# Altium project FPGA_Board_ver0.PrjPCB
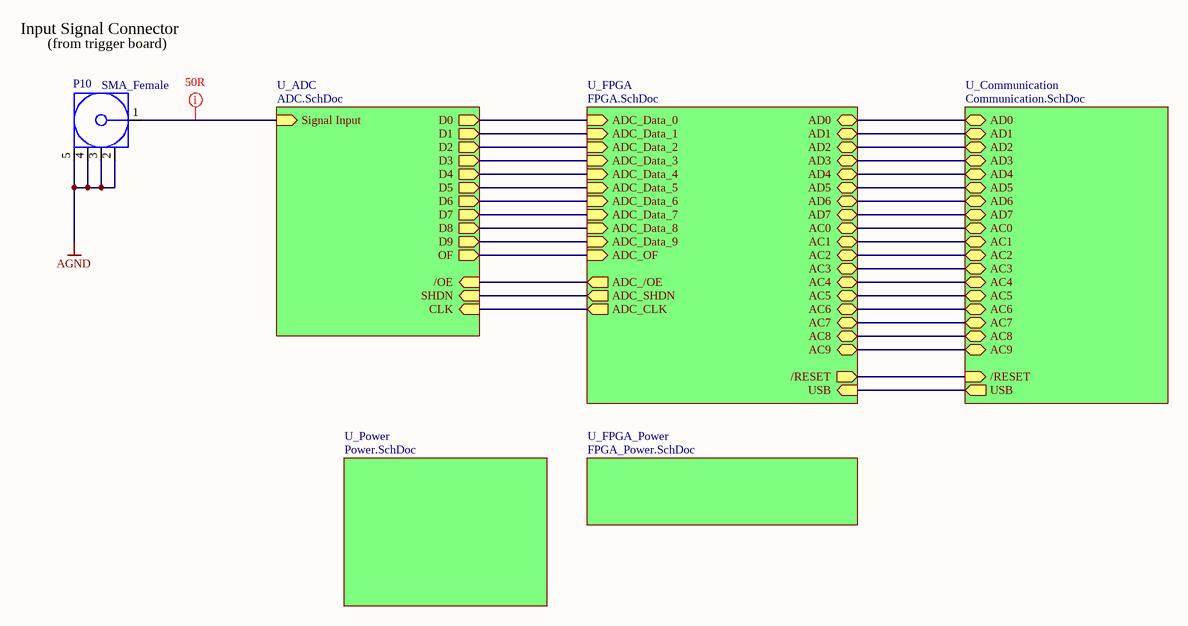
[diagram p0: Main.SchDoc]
6 sheets, 303 parts. Net scope: hierarchical (ports join the sheet entries above them; power ports are global).
Board file: FPGA_Board.PcbDoc
Sheets:
  Main.SchDoc
    U_ADC = ADC.SchDoc
    U_Communication = Communication.SchDoc
    U_FPGA = FPGA.SchDoc
    U_FPGA_Power = FPGA_Power.SchDoc
    U_Power = Power.SchDoc

## Sheet Main.SchDoc
size A4

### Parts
P10  SMA_Female  [SMA5.08-H]

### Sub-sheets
U_ADC = ADC.SchDoc: Signal Input (in), D0 (out), D1 (out), D2 (out), D3 (out), D4 (out), D5 (out), D6 (out), D7 (out), D8 (out), D9 (out), OF (out), CLK (in), SHDN (in), /OE (in)
U_Communication = Communication.SchDoc: AD0 (bidir), AD1 (bidir), AD2 (bidir), AD3 (bidir), AD4 (bidir), AD5 (bidir), AD6 (bidir), AD7 (bidir), AC0 (bidir), AC1 (bidir), AC2 (bidir), AC3 (bidir), AC4 (bidir), AC5 (bidir), AC6 (bidir), AC7 (bidir), AC8 (bidir), AC9 (bidir), /RESET (in), USB (out)
U_FPGA = FPGA.SchDoc: ADC_Data_0 (in), ADC_Data_1 (in), ADC_Data_2 (in), ADC_Data_3 (in), ADC_Data_4 (in), ADC_Data_5 (in), ADC_Data_6 (in), ADC_Data_7 (in), ADC_Data_8 (in), ADC_Data_9 (in), ADC_CLK (out), ADC_OF (in), ADC_/OE (out), ADC_SHDN (out), AD0 (bidir), AD1 (bidir), AD2 (bidir), AD3 (bidir), AD4 (bidir), AD5 (bidir), AD6 (bidir), AD7 (bidir), AC0 (bidir), AC1 (bidir), AC2 (bidir), AC3 (bidir), AC4 (bidir), AC5 (bidir), AC6 (bidir), AC7 (bidir), AC8 (bidir), AC9 (bidir), /RESET (out), USB (in)
U_FPGA_Power = FPGA_Power.SchDoc: no entries
U_Power = Power.SchDoc: no entries

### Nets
AGND: P10.2(GND) P10.3(GND) P10.4(GND) P10.5(GND)
/RESET: sheet U_Communication//RESET, sheet U_FPGA//RESET
NetC16_2: P10.1(Signal) ; sheet U_ADC/Signal Input
NetC41_2: sheet U_Communication/USB, sheet U_FPGA/USB
NetR41_2: sheet U_Communication/AC9, sheet U_FPGA/AC9
NetR42_2: sheet U_Communication/AC8, sheet U_FPGA/AC8
NetR43_2: sheet U_Communication/AC7, sheet U_FPGA/AC7
NetR44_2: sheet U_Communication/AC6, sheet U_FPGA/AC6
NetR45_2: sheet U_Communication/AC5, sheet U_FPGA/AC5
NetR51_2: sheet U_Communication/AC4, sheet U_FPGA/AC4
NetR54_2: sheet U_Communication/AC3, sheet U_FPGA/AC3
NetR55_2: sheet U_Communication/AC2, sheet U_FPGA/AC2
NetR56_2: sheet U_Communication/AC1, sheet U_FPGA/AC1
NetR61_2: sheet U_Communication/AC0, sheet U_FPGA/AC0
NetR66_2: sheet U_Communication/AD7, sheet U_FPGA/AD7
NetR67_2: sheet U_Communication/AD6, sheet U_FPGA/AD6
NetR68_2: sheet U_Communication/AD5, sheet U_FPGA/AD5
NetR71_2: sheet U_Communication/AD4, sheet U_FPGA/AD4
NetR75_2: sheet U_Communication/AD3, sheet U_FPGA/AD3
NetR78_2: sheet U_Communication/AD2, sheet U_FPGA/AD2
NetR79_2: sheet U_Communication/AD1, sheet U_FPGA/AD1
NetR80_2: sheet U_Communication/AD0, sheet U_FPGA/AD0
NetU1_9: sheet U_ADC/CLK, sheet U_FPGA/ADC_CLK
NetU1_10: sheet U_ADC/SHDN, sheet U_FPGA/ADC_SHDN
NetU1_11: sheet U_ADC//OE, sheet U_FPGA/ADC_/OE
NetU1_16: sheet U_ADC/D0, sheet U_FPGA/ADC_Data_0
NetU1_17: sheet U_ADC/D1, sheet U_FPGA/ADC_Data_1
NetU1_18: sheet U_ADC/D2, sheet U_FPGA/ADC_Data_2
NetU1_19: sheet U_ADC/D3, sheet U_FPGA/ADC_Data_3
NetU1_22: sheet U_ADC/D4, sheet U_FPGA/ADC_Data_4
NetU1_23: sheet U_ADC/D5, sheet U_FPGA/ADC_Data_5
NetU1_24: sheet U_ADC/D6, sheet U_FPGA/ADC_Data_6
NetU1_25: sheet U_ADC/D7, sheet U_FPGA/ADC_Data_7
NetU1_26: sheet U_ADC/D8, sheet U_FPGA/ADC_Data_8
NetU1_27: sheet U_ADC/D9, sheet U_FPGA/ADC_Data_9
NetU1_28: sheet U_ADC/OF, sheet U_FPGA/ADC_OF

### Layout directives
net class 50R: NetC16_2

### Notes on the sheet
- Input Signal Connector
- (from trigger board)

## Sheet ADC.SchDoc
size A4
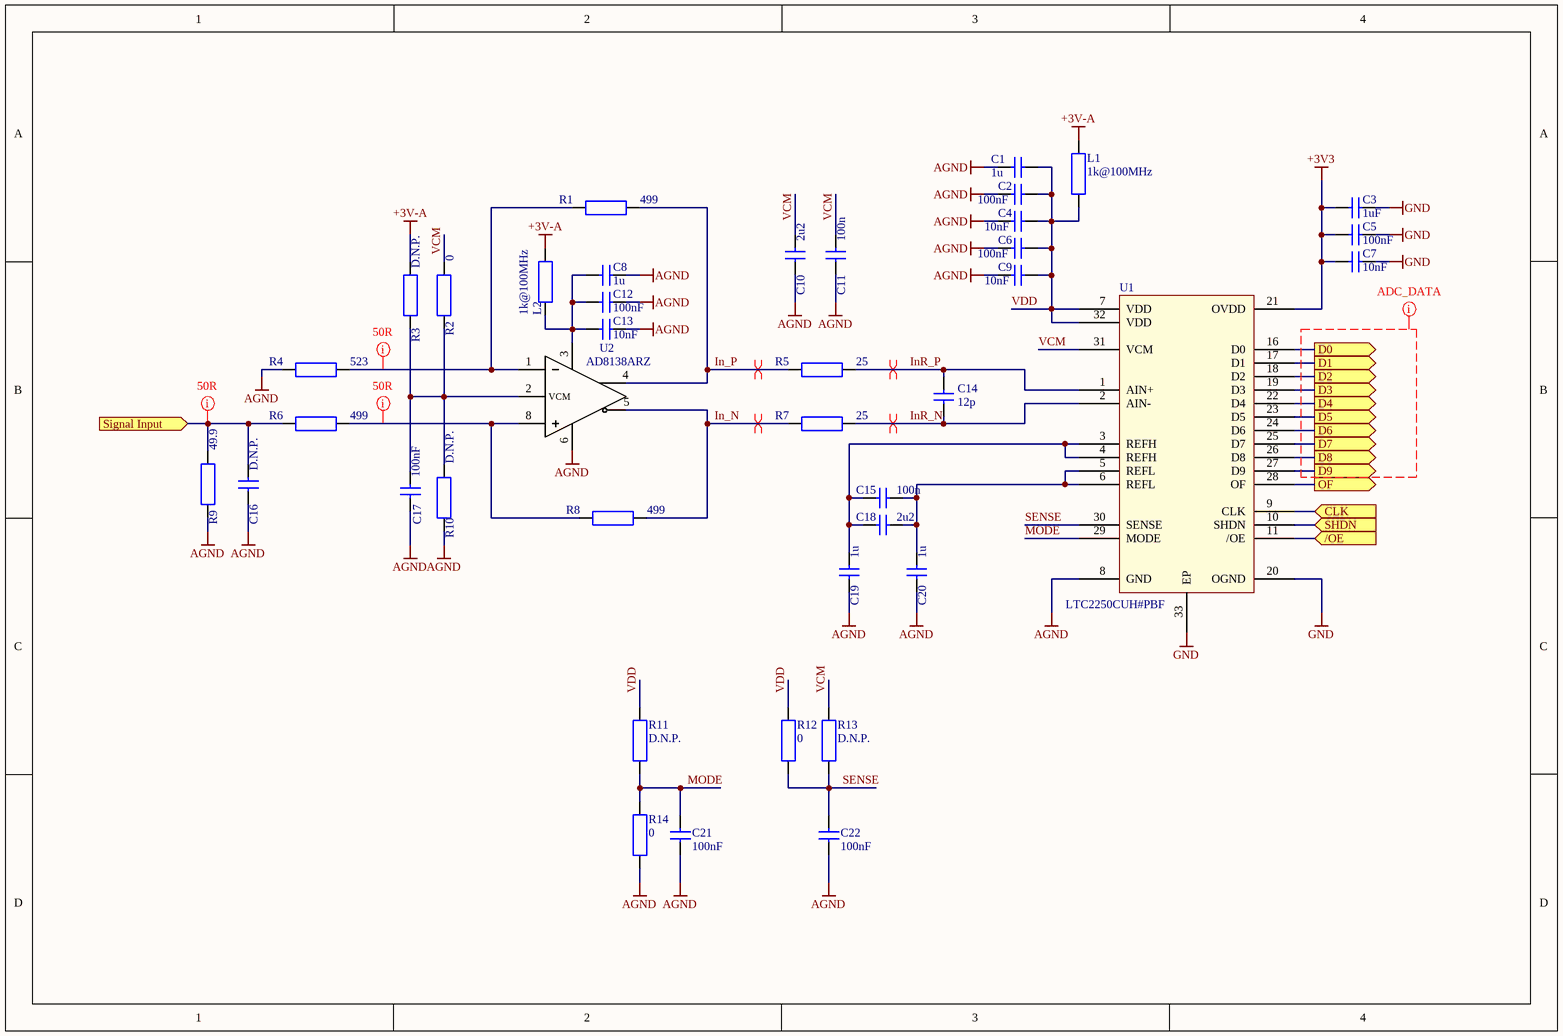
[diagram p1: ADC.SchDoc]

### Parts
C1  1u  [SMD_CAPACITOR_0603]
C2  100nF  [SMD_CAPACITOR_0603]
C3  1uF  [SMD_CAPACITOR_0603]
C4  10nF  [SMD_CAPACITOR_0603]
C5  100nF  [SMD_CAPACITOR_0603]
C6  100nF  [SMD_CAPACITOR_0603]
C7  10nF  [SMD_CAPACITOR_0603]
C8  1u  [SMD_CAPACITOR_0603]
C9  10nF  [SMD_CAPACITOR_0603]
C10  2u2  [SMD_CAPACITOR_0603]
C11  100n  [SMD_CAPACITOR_0603]
C12  100nF  [SMD_CAPACITOR_0603]
C13  10nF  [SMD_CAPACITOR_0603]
C14  12p  [SMD_CAPACITOR_0603]
C15  100n  [SMD_CAPACITOR_0603]
C16  D.N.P.  [SMD_CAPACITOR_0603]
C17  100nF  [SMD_CAPACITOR_0603]
C18  2u2  [SMD_CAPACITOR_0603]
C19  1u  [SMD_CAPACITOR_0603]
C20  1u  [SMD_CAPACITOR_0603]
C21  100nF  [SMD_CAPACITOR_0603]
C22  100nF  [SMD_CAPACITOR_0603]
L1  1k@100MHz  [SMD_RES_0603]
L2  1k@100MHz  [SMD_RES_0603]
R1  499  [SMD_RES_0603]
R2  0  [SMD_RES_0603]
R3  D.N.P.  [SMD_RES_0603]
R4  523  [SMD_RES_0603]
R5  25  [SMD_RES_0603]
R6  499  [SMD_RES_0603]
R7  25  [SMD_RES_0603]
R8  499  [SMD_RES_0603]
R9  49.9  [SMD_RES_0603]
R10  D.N.P.  [SMD_RES_0603]
R11  D.N.P.  [SMD_RES_0603]
R12  0  [SMD_RES_0603]
R13  D.N.P.  [SMD_RES_0603]
R14  0  [SMD_RES_0603]
U1  LTC2250CUH#PBF  [QFN-32_5mm_x_5mm]
U2  AD8138ARZ  [SMD_SOIC-8]

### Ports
/OE (in), CLK (in), D0 (out), D1 (out), D2 (out), D3 (out), D4 (out), D5 (out), D6 (out), D7 (out), D8 (out), D9 (out), OF (out), SHDN (in), Signal Input (in)

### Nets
+3V3: C3.1 C5.1 C7.1 U1.21(OVDD)
+3V-A: L1.2 L2.2 R3.2
AGND: C1.2 C2.2 C4.2 C6.2 C8.2 C9.2 C10.1 C11.1 C12.2 C13.2 C16.1 C17.1 C19.1 C20.1 C21.2 C22.2 R4.1 R9.1 R10.1 R14.1 U1.8(GND) U2.6
GND: C3.2 C5.2 C7.2 U1.20(OGND) U1.33(EP)
In_N: R7.1 R8.2 U2.5
In_P: R1.2 R5.1 U2.4
InR_N: C14.1 R7.2 U1.2(AIN-)
InR_P: C14.2 R5.2 U1.1(AIN+)
MODE: C21.1 R11.1 R14.2 U1.29(MODE)
SENSE: C22.1 R12.1 R13.1 U1.30(SENSE)
VCM: C10.2 C11.2 R2.2 R13.2 U1.31(VCM)
VDD: C1.1 C2.1 C4.1 C6.1 C9.1 L1.1 R11.2 R12.2 U1.7(VDD) U1.32(VDD)
NetC8_1: C8.1 C12.1 C13.1 L2.1 U2.3
NetC15_1: C15.1 C18.1 C20.2 U1.5(REFL) U1.6(REFL)
NetC15_2: C15.2 C18.2 C19.2 U1.3(REFH) U1.4(REFH)
NetC16_2: C16.2 R6.1 R9.2 ; port Signal Input
NetC17_2: C17.2 R2.1 R3.1 R10.2 U2.2(VCM)
NetR1_1: R1.1 R4.2 U2.1
NetR6_2: R6.2 R8.1 U2.8
NetU1_9: U1.9(CLK) ; port CLK
NetU1_10: U1.10(SHDN) ; port SHDN
NetU1_11: U1.11(/OE) ; port /OE
NetU1_16: U1.16(D0) ; port D0
NetU1_17: U1.17(D1) ; port D1
NetU1_18: U1.18(D2) ; port D2
NetU1_19: U1.19(D3) ; port D3
NetU1_22: U1.22(D4) ; port D4
NetU1_23: U1.23(D5) ; port D5
NetU1_24: U1.24(D6) ; port D6
NetU1_25: U1.25(D7) ; port D7
NetU1_26: U1.26(D8) ; port D8
NetU1_27: U1.27(D9) ; port D9
NetU1_28: U1.28(OF) ; port OF

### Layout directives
net class 50R: NetC16_2, NetR1_1, NetR6_2
differential pair: In_N, In_P, InR_N, InR_P
net class ADC_DATA: (no net found under the mark)

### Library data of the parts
C1-C22 = Capacitor
L1 L2 = EMI_Ferrite_bead
R1-R14 = Resistor
U1 = LTC2250CUH#PBF: Analog to digital converter_10bit_105MS/s
U2 = AD8138ARZ: Low Distortion,Differential ADC Driver

## Sheet Communication.SchDoc
size A4
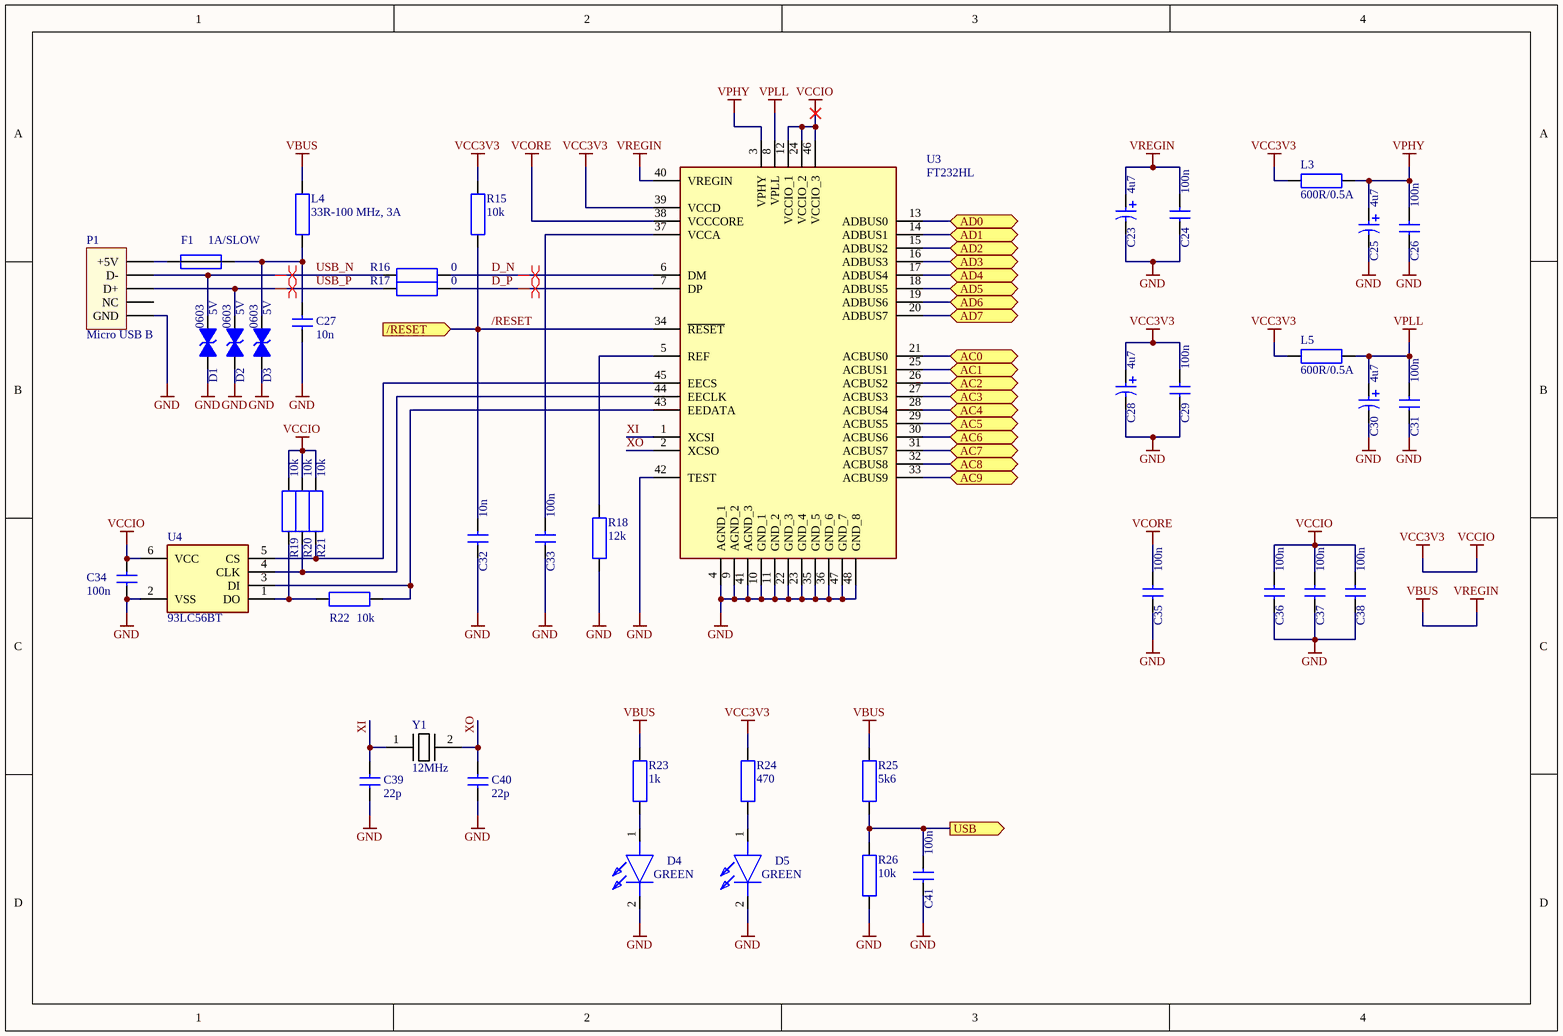
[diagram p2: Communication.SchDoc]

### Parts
C23  4u7  [SMD_CAPACITOR_POL_A_3216]
C24  100n  [SMD_CAPACITOR_0402]
C25  4u7  [SMD_CAPACITOR_POL_A_3216]
C26  100n  [SMD_CAPACITOR_0402]
C27  10n  [SMD_CAPACITOR_0603]
C28  4u7  [SMD_CAPACITOR_POL_A_3216]
C29  100n  [SMD_CAPACITOR_0402]
C30  4u7  [SMD_CAPACITOR_POL_A_3216]
C31  100n  [SMD_CAPACITOR_0402]
C32  10n  [SMD_CAPACITOR_0603]
C33  100n  [SMD_CAPACITOR_0402]
C34  100n  [SMD_CAPACITOR_0603]
C35  100n  [SMD_CAPACITOR_0402]
C36  100n  [SMD_CAPACITOR_0402]
C37  100n  [SMD_CAPACITOR_0402]
C38  100n  [SMD_CAPACITOR_0402]
C39  22p  [SMD_CAPACITOR_0603]
C40  22p  [SMD_CAPACITOR_0603]
C41  100n  [SMD_CAPACITOR_0603]
D1  5V  Package: 0603  [sm_esd_0603]
D2  5V  Package: 0603  [sm_esd_0603]
D3  5V  Package: 0603  [sm_esd_0603]
D4  GREEN  [SMD_LED_0603]
D5  GREEN  [SMD_LED_0603]
F1  1A/SLOW  [SMD_RESISTOR_1206]
L3  600R/0.5A  [SMD_RES_0603]
L4  33R-100 MHz, 3A  [SMD_RES_0603]
L5  600R/0.5A  [SMD_RES_0603]
P1  Micro USB B  [SMD_USB_MICRO_B]
R15  10k  [SMD_RES_0603]
R16  0  [SMD_RES_0603]
R17  0  [SMD_RES_0603]
R18  12k  [SMD_RES_0603]
R19  10k  [SMD_RES_0603]
R20  10k  [SMD_RES_0603]
R21  10k  [SMD_RES_0603]
R22  10k  [SMD_RES_0603]
R23  1k  [SMD_RES_0603]
R24  470  [SMD_RES_0603]
R25  5k6  [SMD_RES_0603]
R26  10k  [SMD_RES_0603]
U3  FT232HL  [QFP50P900X900X160-48N]
U4  93LC56BT  [SOT95P270X145-6N]
Y1  12MHz  [SMD_XTAL_HC-49]

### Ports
/RESET (in), AC0 (bidir), AC1 (bidir), AC2 (bidir), AC3 (bidir), AC4 (bidir), AC5 (bidir), AC6 (bidir), AC7 (bidir), AC8 (bidir), AC9 (bidir), AD0 (bidir), AD1 (bidir), AD2 (bidir), AD3 (bidir), AD4 (bidir), AD5 (bidir), AD6 (bidir), AD7 (bidir), USB (out)

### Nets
GND: C23.2 C24.1 C25.2 C26.1 C27.1 C28.2 C29.1 C30.2 C31.1 C32.1 C33.1 C34.1 C35.1 C36.1 C37.1 C38.1 C39.1 C40.1 C41.1 D1.1 D2.1 D3.1 D4.2(K) D5.2(K) P1.5(GND) R18.1 R26.1 U3.4(AGND_1) U3.9(AGND_2) U3.10(GND_1) U3.11(GND_2) U3.22(GND_3) U3.23(GND_4) U3.35(GND_5) U3.36(GND_6) U3.41(AGND_3) U3.42(TEST) U3.47(GND_7) U3.48(GND_8) U4.2(VSS)
VBUS: C23.1 C24.2 L4.2 R23.2 R25.2 U3.40(VREGIN)  [also labelled VREGIN]
VCC3V3: C28.1 C29.2 C34.2 C36.2 C37.2 C38.2 L3.2 L5.2 R15.2 R19.2 R20.2 R21.2 R24.2 U3.12(VCCIO_1) U3.24(VCCIO_2) U3.39(VCCD) U3.46(VCCIO_3) U4.6(VCC)  [also labelled VCCIO]
VCORE: C35.2 U3.38(VCCCORE)
VPHY: C25.1 C26.2 L3.1 U3.3(VPHY)
VPLL: C30.1 C31.2 L5.1 U3.8(VPLL)
/RESET: C32.2 R15.1 U3.34(~{RESET}) ; port /RESET
D_N: R16.2 U3.6(DM)
D_P: R17.2 U3.7(DP)
USB_N: D1.2 P1.2(D-) R16.1
USB_P: D2.2 P1.3(D+) R17.1
XI: C39.2 U3.1(XCSI) Y1.1(CRYSTAL_1)
XO: C40.2 U3.2(XCSO) Y1.2(CRYSTAL_2)
NetC27_2: C27.2 D3.2 F1.2 L4.1
NetC33_2: C33.2 U3.37(VCCA)
NetC41_2: C41.2 R25.1 R26.2 ; port USB
NetD4_1: D4.1(A) R23.1
NetD5_1: D5.1(A) R24.1
NetF1_1: F1.1 P1.1(+5V)
NetR18_2: R18.2 U3.5(REF)
NetR19_1: R19.1 R22.1 U4.1(DO)
NetR20_1: R20.1 U3.44(EECLK) U4.4(CLK)
NetR21_1: R21.1 U3.45(EECS) U4.5(CS)
NetR22_2: R22.2 U3.43(EEDATA) U4.3(DI)
NetR41_2: U3.33(ACBUS9) ; port AC9
NetR42_2: U3.32(ACBUS8) ; port AC8
NetR43_2: U3.31(ACBUS7) ; port AC7
NetR44_2: U3.30(ACBUS6) ; port AC6
NetR45_2: U3.29(ACBUS5) ; port AC5
NetR51_2: U3.28(ACBUS4) ; port AC4
NetR54_2: U3.27(ACBUS3) ; port AC3
NetR55_2: U3.26(ACBUS2) ; port AC2
NetR56_2: U3.25(ACBUS1) ; port AC1
NetR61_2: U3.21(ACBUS0) ; port AC0
NetR66_2: U3.20(ADBUS7) ; port AD7
NetR67_2: U3.19(ADBUS6) ; port AD6
NetR68_2: U3.18(ADBUS5) ; port AD5
NetR71_2: U3.17(ADBUS4) ; port AD4
NetR75_2: U3.16(ADBUS3) ; port AD3
NetR78_2: U3.15(ADBUS2) ; port AD2
NetR79_2: U3.14(ADBUS1) ; port AD1
NetR80_2: U3.13(ADBUS0) ; port AD0

Not connected (* = marked no-connect by the designer): P1 4(NC)

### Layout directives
differential pair: D_N, D_P, USB_N, USB_P

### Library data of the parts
C23 C25 C28 C30 = Capacitor_pol
C24 C26 C27 C29 C31-C41 = Capacitor
D1-D3 = ESD_suppressor_bidir_5V: ESD suppressor, 5V; Manufacturer: Bourns; Part Number: 652-CG0603MLC-05LEA
D4 D5 = LED
F1 = Fuse
L3-L5 = EMI_Ferrite_bead
P1 = USB_Micro_B: Micro USB Type B
R15-R26 = Resistor
U3 = FT232HL-REEL: Single Channel Hi-Speed USB to Multipurpose UART/FIFO
U4 = 93LC56BT-E_OT: EEPROM
Y1 = XTAL_2pin

## Sheet FPGA.SchDoc
size A3
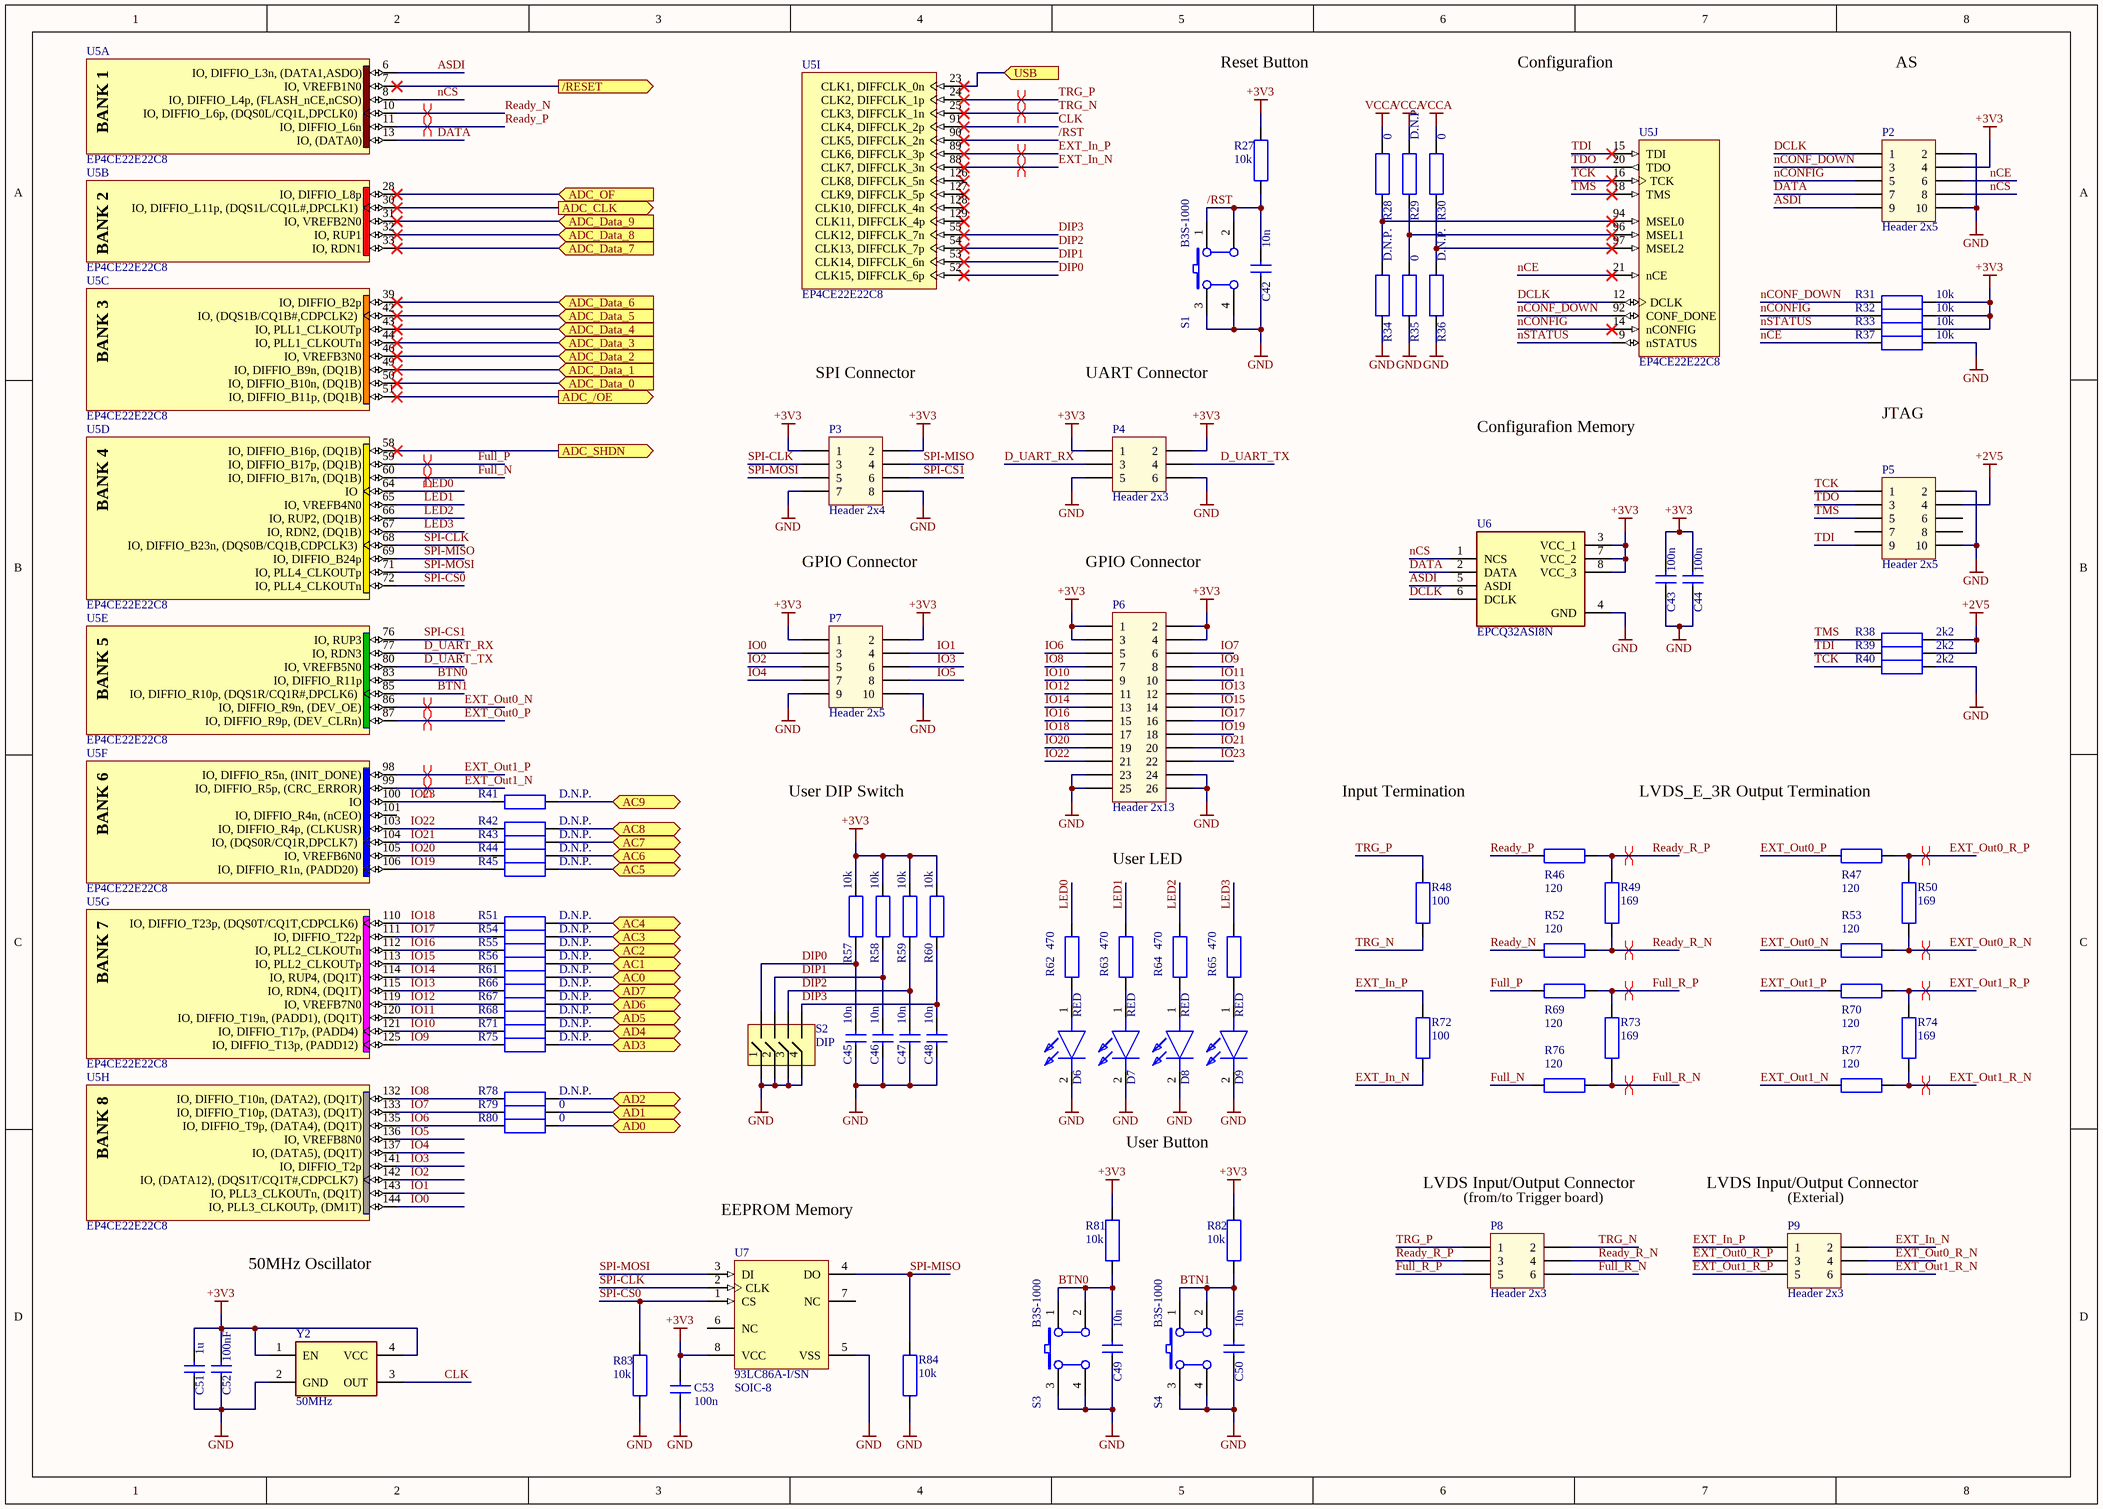
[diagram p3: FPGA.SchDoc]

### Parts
C42  10n  [SMD_CAPACITOR_0603]
C43  100n  [SMD_CAPACITOR_0603]
C44  100n  [SMD_CAPACITOR_0603]
C45  10n  [SMD_CAPACITOR_0603]
C46  10n  [SMD_CAPACITOR_0603]
C47  10n  [SMD_CAPACITOR_0603]
C48  10n  [SMD_CAPACITOR_0603]
C49  10n  [SMD_CAPACITOR_0603]
C50  10n  [SMD_CAPACITOR_0603]
C51  1u  [SMD_CAPACITOR_0603]
C52  100nF  [SMD_CAPACITOR_0603]
C53  100n  [SMD_CAPACITOR_0603]
D6  RED  [SMD_LED_0603]
D7  RED  [SMD_LED_0603]
D8  RED  [SMD_LED_0603]
D9  RED  [SMD_LED_0603]
P2  Header 2x5  [THT_HEADER_100MIL_2X5_MALE_SHROUDED]
P3  Header 2x4  [THT_HEADER_100MIL_2X4_MALE_SHROUDED]
P4  Header 2x3  [THT_HEADER_100MIL_2X3_MALE_SHROUDED]
P5  Header 2x5  [THT_HEADER_100MIL_2X5_MALE_SHROUDED]
P6  Header 2x13  [THT_HEADER_2x13]
P7  Header 2x5  [THT_HEADER_100MIL_2X5_MALE_SHROUDED]
P8  Header 2x3  [THT_HEADER_100MIL_2X3_MALE_SHROUDED]
P9  Header 2x3  [THT_HEADER_100MIL_2X3_MALE_SHROUDED]
R27  10k  [SMD_RES_0603]
R28  0  [SMD_RES_0603]
R29  D.N.P.  [SMD_RES_0603]
R30  0  [SMD_RES_0603]
R31  10k  [SMD_RES_0603]
R32  10k  [SMD_RES_0603]
R33  10k  [SMD_RES_0603]
R34  D.N.P.  [SMD_RES_0603]
R35  0  [SMD_RES_0603]
R36  D.N.P.  [SMD_RES_0603]
R37  10k  [SMD_RES_0603]
R38  2k2  [SMD_RES_0603]
R39  2k2  [SMD_RES_0603]
R40  2k2  [SMD_RES_0603]
R41  D.N.P.  [SMD_RES_0603]
R42  D.N.P.  [SMD_RES_0603]
R43  D.N.P.  [SMD_RES_0603]
R44  D.N.P.  [SMD_RES_0603]
R45  D.N.P.  [SMD_RES_0603]
R46  120  [SMD_RES_0603]
R47  120  [SMD_RES_0603]
R48  100  [SMD_RES_0603]
R49  169  [SMD_RES_0603]
R50  169  [SMD_RES_0603]
R51  D.N.P.  [SMD_RES_0603]
R52  120  [SMD_RES_0603]
R53  120  [SMD_RES_0603]
R54  D.N.P.  [SMD_RES_0603]
R55  D.N.P.  [SMD_RES_0603]
R56  D.N.P.  [SMD_RES_0603]
R57  10k  [SMD_RES_0603]
R58  10k  [SMD_RES_0603]
R59  10k  [SMD_RES_0603]
R60  10k  [SMD_RES_0603]
R61  D.N.P.  [SMD_RES_0603]
R62  470  [SMD_RES_0603]
R63  470  [SMD_RES_0603]
R64  470  [SMD_RES_0603]
R65  470  [SMD_RES_0603]
R66  D.N.P.  [SMD_RES_0603]
R67  D.N.P.  [SMD_RES_0603]
R68  D.N.P.  [SMD_RES_0603]
R69  120  [SMD_RES_0603]
R70  120  [SMD_RES_0603]
R71  D.N.P.  [SMD_RES_0603]
R72  100  [SMD_RES_0603]
R73  169  [SMD_RES_0603]
R74  169  [SMD_RES_0603]
R75  D.N.P.  [SMD_RES_0603]
R76  120  [SMD_RES_0603]
R77  120  [SMD_RES_0603]
R78  D.N.P.  [SMD_RES_0603]
R79  0  [SMD_RES_0603]
R80  0  [SMD_RES_0603]
R81  10k  [SMD_RES_0603]
R82  10k  [SMD_RES_0603]
R83  10k  [SMD_RES_0603]
R84  10k  [SMD_RES_0603]
S1  B3S-1000  [B3S-1000]
S2  Package: DIP  [DIP switch, SPST, 4x]  (hidden comment: DIP switch, SPST, 4x)
S3  B3S-1000  [B3S-1000]
S4  B3S-1000  [B3S-1000]
U5  EP4CE22E22C8  [EQFP144_N]  (parts A,B,C,D,E,F,G,H,I,J of 13)
U6  EPCQ32ASI8N  [SMD_SOIC-8]
U7  93LC86A-I/SN  Package: SOIC-8  [SO8_M]
Y2  50MHz  [CA32C5003HLT]

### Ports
/RESET (out), AC0 (bidir), AC1 (bidir), AC2 (bidir), AC3 (bidir), AC4 (bidir), AC5 (bidir), AC6 (bidir), AC7 (bidir), AC8 (bidir), AC9 (bidir), AD0 (bidir), AD1 (bidir), AD2 (bidir), AD3 (bidir), AD4 (bidir), AD5 (bidir), AD6 (bidir), AD7 (bidir), ADC_/OE (out), ADC_CLK (out), ADC_Data_0 (in), ADC_Data_1 (in), ADC_Data_2 (in), ADC_Data_3 (in), ADC_Data_4 (in), ADC_Data_5 (in), ADC_Data_6 (in), ADC_Data_7 (in), ADC_Data_8 (in), ADC_Data_9 (in), ADC_OF (in), ADC_SHDN (out), USB (in)

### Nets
+2V5: P5.4 R38.2 R39.2
+3V3: C43.2 C44.2 C51.1 C52.1 C53.2 P2.4 P3.1 P3.2 P4.1 P4.2 P6.1 P6.2 P6.3 P6.4 P7.1 P7.2 R27.2 R31.2 R32.2 R33.2 R57.2 R58.2 R59.2 R60.2 R81.2 R82.2 U6.3(VCC_1) U6.7(VCC_2) U6.8(VCC_3) U7.8(VCC) Y2.1(EN) Y2.4(VCC)
GND: C42.2 C43.1 C44.1 C45.1 C46.1 C47.1 C48.1 C49.2 C50.2 C51.2 C52.2 C53.1 D6.2(K) D7.2(K) D8.2(K) D9.2(K) P2.2 P2.10 P3.7 P3.8 P4.5 P4.6 P5.2 P5.10 P6.23 P6.24 P6.25 P6.26 P7.9 P7.10 R34.1 R35.1 R36.1 R37.2 R40.2 R83.1 R84.1 S1.3(B1) S1.4(A1) S2.1 S2.3 S2.5 S2.7 S3.3(B1) S3.4(A1) S4.3(B1) S4.4(A1) U6.4(GND) U7.5(VSS) Y2.2(GND)
VCCA: R28.2 R29.2 R30.2
/RESET: U5.7(IO,_VREFB1N0) ; port /RESET
/RST: C42.1 R27.1 S1.1(A0) S1.2(B0) U5.90(CLK5,_DIFFCLK_2n)
ASDI: P2.9 U5.6(IO,_DIFFIO_L3n,_(DATA1,ASDO)) U6.5(ASDI)
BTN0: C49.1 R81.1 S3.1(A0) S3.2(B0) U5.83(IO,_DIFFIO_R11p)
BTN1: C50.1 R82.1 S4.1(A0) S4.2(B0) U5.85(IO,_DIFFIO_R10p,_(DQS1R/CQ1R#,DPCLK6))
CLK: U5.91(CLK4,_DIFFCLK_2p) Y2.3(OUT)
D_UART_RX: P4.3 U5.77(IO,_RDN3)
D_UART_TX: P4.4 U5.80(IO,_VREFB5N0)
DATA: P2.7 U5.13(IO,_(DATA0)) U6.2(DATA)
DCLK: P2.1 U5.12(DCLK) U6.6(DCLK)
DIP0: C45.2 R57.1 S2.2 U5.52(CLK15,_DIFFCLK_6p)
DIP1: C46.2 R58.1 S2.4 U5.53(CLK14,_DIFFCLK_6n)
DIP2: C47.2 R59.1 S2.6 U5.54(CLK13,_DIFFCLK_7p)
DIP3: C48.2 R60.1 S2.8 U5.55(CLK12,_DIFFCLK_7n)
EXT_In_N: P9.2 R72.1 U5.88(CLK7,_DIFFCLK_3n)
EXT_In_P: P9.1 R72.2 U5.89(CLK6,_DIFFCLK_3p)
EXT_Out0_N: R53.1 U5.86(IO,_DIFFIO_R9n,_(DEV_OE))
EXT_Out0_P: R47.1 U5.87(IO,_DIFFIO_R9p,_(DEV_CLRn))
EXT_Out0_R_N: P9.4 R50.1 R53.2
EXT_Out0_R_P: P9.3 R47.2 R50.2
EXT_Out1_N: R77.1 U5.99(IO,_DIFFIO_R5p,_(CRC_ERROR))
EXT_Out1_P: R70.1 U5.98(IO,_DIFFIO_R5n,_(INIT_DONE))
EXT_Out1_R_N: P9.6 R74.1 R77.2
EXT_Out1_R_P: P9.5 R70.2 R74.2
Full_N: R76.1 U5.60(IO,_DIFFIO_B17n,_(DQ1B))
Full_P: R69.1 U5.59(IO,_DIFFIO_B17p,_(DQ1B))
Full_R_N: P8.6 R73.1 R76.2
Full_R_P: P8.5 R69.2 R73.2
IO0: P7.3 U5.144(IO,_PLL3_CLKOUTp,_(DM1T))
IO1: P7.4 U5.143(IO,_PLL3_CLKOUTn,_(DQ1T))
IO2: P7.5 U5.142(IO,_(DATA12),_(DQS1T/CQ1T#,CDPCLK7))
IO3: P7.6 U5.141(IO,_DIFFIO_T2p)
IO4: P7.7 U5.137(IO,_(DATA5),_(DQ1T))
IO5: P7.8 U5.136(IO,_VREFB8N0)
IO6: P6.5 R80.1 U5.135(IO,_DIFFIO_T9p,_(DATA4),_(DQ1T))
IO7: P6.6 R79.1 U5.133(IO,_DIFFIO_T10p,_(DATA3),_(DQ1T))
IO8: P6.7 R78.1 U5.132(IO,_DIFFIO_T10n,_(DATA2),_(DQ1T))
IO9: P6.8 R75.1 U5.125(IO,_DIFFIO_T13p,_(PADD12))
IO10: P6.9 R71.1 U5.121(IO,_DIFFIO_T17p,_(PADD4))
IO11: P6.10 R68.1 U5.120(IO,_DIFFIO_T19n,_(PADD1),_(DQ1T))
IO12: P6.11 R67.1 U5.119(IO,_VREFB7N0)
IO13: P6.12 R66.1 U5.115(IO,_RDN4,_(DQ1T))
IO14: P6.13 R61.1 U5.114(IO,_RUP4,_(DQ1T))
IO15: P6.14 R56.1 U5.113(IO,_PLL2_CLKOUTp)
IO16: P6.15 R55.1 U5.112(IO,_PLL2_CLKOUTn)
IO17: P6.16 R54.1 U5.111(IO,_DIFFIO_T22p)
IO18: P6.17 R51.1 U5.110(IO,_DIFFIO_T23p,_(DQS0T/CQ1T,CDPCLK6))
IO19: P6.18 R45.1 U5.106(IO,_DIFFIO_R1n,_(PADD20))
IO20: P6.19 R44.1 U5.105(IO,_VREFB6N0)
IO21: P6.20 R43.1 U5.104(IO,_(DQS0R/CQ1R,DPCLK7))
IO22: P6.21 R42.1 U5.103(IO,_DIFFIO_R4p,_(CLKUSR))
IO23: P6.22 R41.1 U5.100(IO)
LED0: R62.1 U5.64(IO)
LED1: R63.1 U5.65(IO,_VREFB4N0)
LED2: R64.1 U5.66(IO,_RUP2,_(DQ1B))
LED3: R65.1 U5.67(IO,_RDN2,_(DQ1B))
nCE: P2.6 R37.1 U5.21(nCE)
nCONF_DOWN: P2.3 R31.1 U5.92(CONF_DONE)
nCONFIG: P2.5 R32.1 U5.14(nCONFIG)
nCS: P2.8 U5.8(IO,_DIFFIO_L4p,_(FLASH_nCE,nCSO)) U6.1(NCS)
nSTATUS: R33.1 U5.9(nSTATUS)
Ready_N: R52.1 U5.10(IO,_DIFFIO_L6p,_(DQS0L/CQ1L,DPCLK0))
Ready_P: R46.1 U5.11(IO,_DIFFIO_L6n)
Ready_R_N: P8.4 R49.1 R52.2
Ready_R_P: P8.3 R46.2 R49.2
SPI-CLK: P3.3 U5.68(IO,_DIFFIO_B23n,_(DQS0B/CQ1B,CDPCLK3)) U7.2(CLK)
SPI-CS0: R83.2 U5.72(IO,_PLL4_CLKOUTn) U7.1(CS)
SPI-CS1: P3.6 U5.76(IO,_RUP3)
SPI-MISO: P3.4 R84.2 U5.69(IO,_DIFFIO_B24p) U7.4(DO)
SPI-MOSI: P3.5 U5.71(IO,_PLL4_CLKOUTp) U7.3(DI)
TCK: P5.1 R40.1 U5.16(TCK)
TDI: P5.9 R39.1 U5.15(TDI)
TDO: P5.3 U5.20(TDO)
TMS: P5.5 R38.1 U5.18(TMS)
TRG_N: P8.2 R48.1 U5.25(CLK3,_DIFFCLK_1n)
TRG_P: P8.1 R48.2 U5.24(CLK2,_DIFFCLK_1p)
NetC41_2: U5.23(CLK1,_DIFFCLK_0n) ; port USB
NetD6_1: D6.1(A) R62.2
NetD7_1: D7.1(A) R63.2
NetD8_1: D8.1(A) R64.2
NetD9_1: D9.1(A) R65.2
NetR28_1: R28.1 R34.2 U5.94(MSEL0)
NetR29_1: R29.1 R35.2 U5.96(MSEL1)
NetR30_1: R30.1 R36.2 U5.97(MSEL2)
NetR41_2: R41.2 ; port AC9
NetR42_2: R42.2 ; port AC8
NetR43_2: R43.2 ; port AC7
NetR44_2: R44.2 ; port AC6
NetR45_2: R45.2 ; port AC5
NetR51_2: R51.2 ; port AC4
NetR54_2: R54.2 ; port AC3
NetR55_2: R55.2 ; port AC2
NetR56_2: R56.2 ; port AC1
NetR61_2: R61.2 ; port AC0
NetR66_2: R66.2 ; port AD7
NetR67_2: R67.2 ; port AD6
NetR68_2: R68.2 ; port AD5
NetR71_2: R71.2 ; port AD4
NetR75_2: R75.2 ; port AD3
NetR78_2: R78.2 ; port AD2
NetR79_2: R79.2 ; port AD1
NetR80_2: R80.2 ; port AD0
NetU1_9: U5.30(IO,_DIFFIO_L11p,_(DQS1L/CQ1L#,DPCLK1)) ; port ADC_CLK
NetU1_10: U5.58(IO,_DIFFIO_B16p,_(DQ1B)) ; port ADC_SHDN
NetU1_11: U5.51(IO,_DIFFIO_B11p,_(DQ1B)) ; port ADC_/OE
NetU1_16: U5.50(IO,_DIFFIO_B10n,_(DQ1B)) ; port ADC_Data_0
NetU1_17: U5.49(IO,_DIFFIO_B9n,_(DQ1B)) ; port ADC_Data_1
NetU1_18: U5.46(IO,_VREFB3N0) ; port ADC_Data_2
NetU1_19: U5.44(IO,_PLL1_CLKOUTn) ; port ADC_Data_3
NetU1_22: U5.43(IO,_PLL1_CLKOUTp) ; port ADC_Data_4
NetU1_23: U5.42(IO,_(DQS1B/CQ1B#,CDPCLK2)) ; port ADC_Data_5
NetU1_24: U5.39(IO,_DIFFIO_B2p) ; port ADC_Data_6
NetU1_25: U5.33(IO,_RDN1) ; port ADC_Data_7
NetU1_26: U5.32(IO,_RUP1) ; port ADC_Data_8
NetU1_27: U5.31(IO,_VREFB2N0) ; port ADC_Data_9
NetU1_28: U5.28(IO,_DIFFIO_L8p) ; port ADC_OF

Not connected (* = marked no-connect by the designer): P5 6 7 8; U5 101(IO,_DIFFIO_R4n,_(nCEO)) 126(CLK8,_DIFFCLK_5n)* 127(CLK9,_DIFFCLK_5p)* 128(CLK10,_DIFFCLK_4n)* 129(CLK11,_DIFFCLK_4p)*; U7 6(NC) 7(NC)

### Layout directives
differential pair: EXT_In_N, EXT_In_P, EXT_Out0_N, EXT_Out0_P, EXT_Out0_R_N, EXT_Out0_R_P, EXT_Out1_N, EXT_Out1_P, EXT_Out1_R_N, EXT_Out1_R_P, Full_N, Full_P, Full_R_N, Full_R_P, Ready_N, Ready_P, Ready_R_N, Ready_R_P, TRG_N, TRG_P

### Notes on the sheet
- Reset Button
- Configurafion
- AS
- SPI Connector
- UART Connector
- Configurafion Memory
- JTAG
- GPIO Connector
- User DIP Switch
- Input Termination
- LVDS_E_3R Output Termination
- User LED
- User Button
- LVDS Input/Output Connector
- EEPROM Memory
- (near P8) (from/to Trigger board)
- (near P9) (Exterial)
- (near U5) 50MHz Oscillator

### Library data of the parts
C42-C53 = Capacitor
D6-D9 = LED
P2 P5 P7 = Header_2x5
P3 = Header_2x4
P4 P8 P9 = Header_2x3
P6 = Header_2x8_1: Header 2x8
R27-R84 = Resistor
S1 S3 S4 = B3S-1000: SWITCH TACTILE SPST-NO 0.05A 24V; Manufacturer: OMRON
S2 = DIP switch, SPST, 4x: Manufacturer: Wurth Electronics; Part Number: 418117270904
U5 = EP4CE22E22C8: Cyclone IV Family FPGA, 2V Core, 79 I/O Pins, 4 PLLs, 144-Pin QFP, Speed Grade 8, Commercial Grade
U6 = EPCS16SI8N: Serial Configuration Memory
U7 = 93LC86A-I/SN: Manufacturer: Microchip
Y2 = CA32C5003HLT: Crystal or Oscillator

## Sheet FPGA_Power.SchDoc
size A3
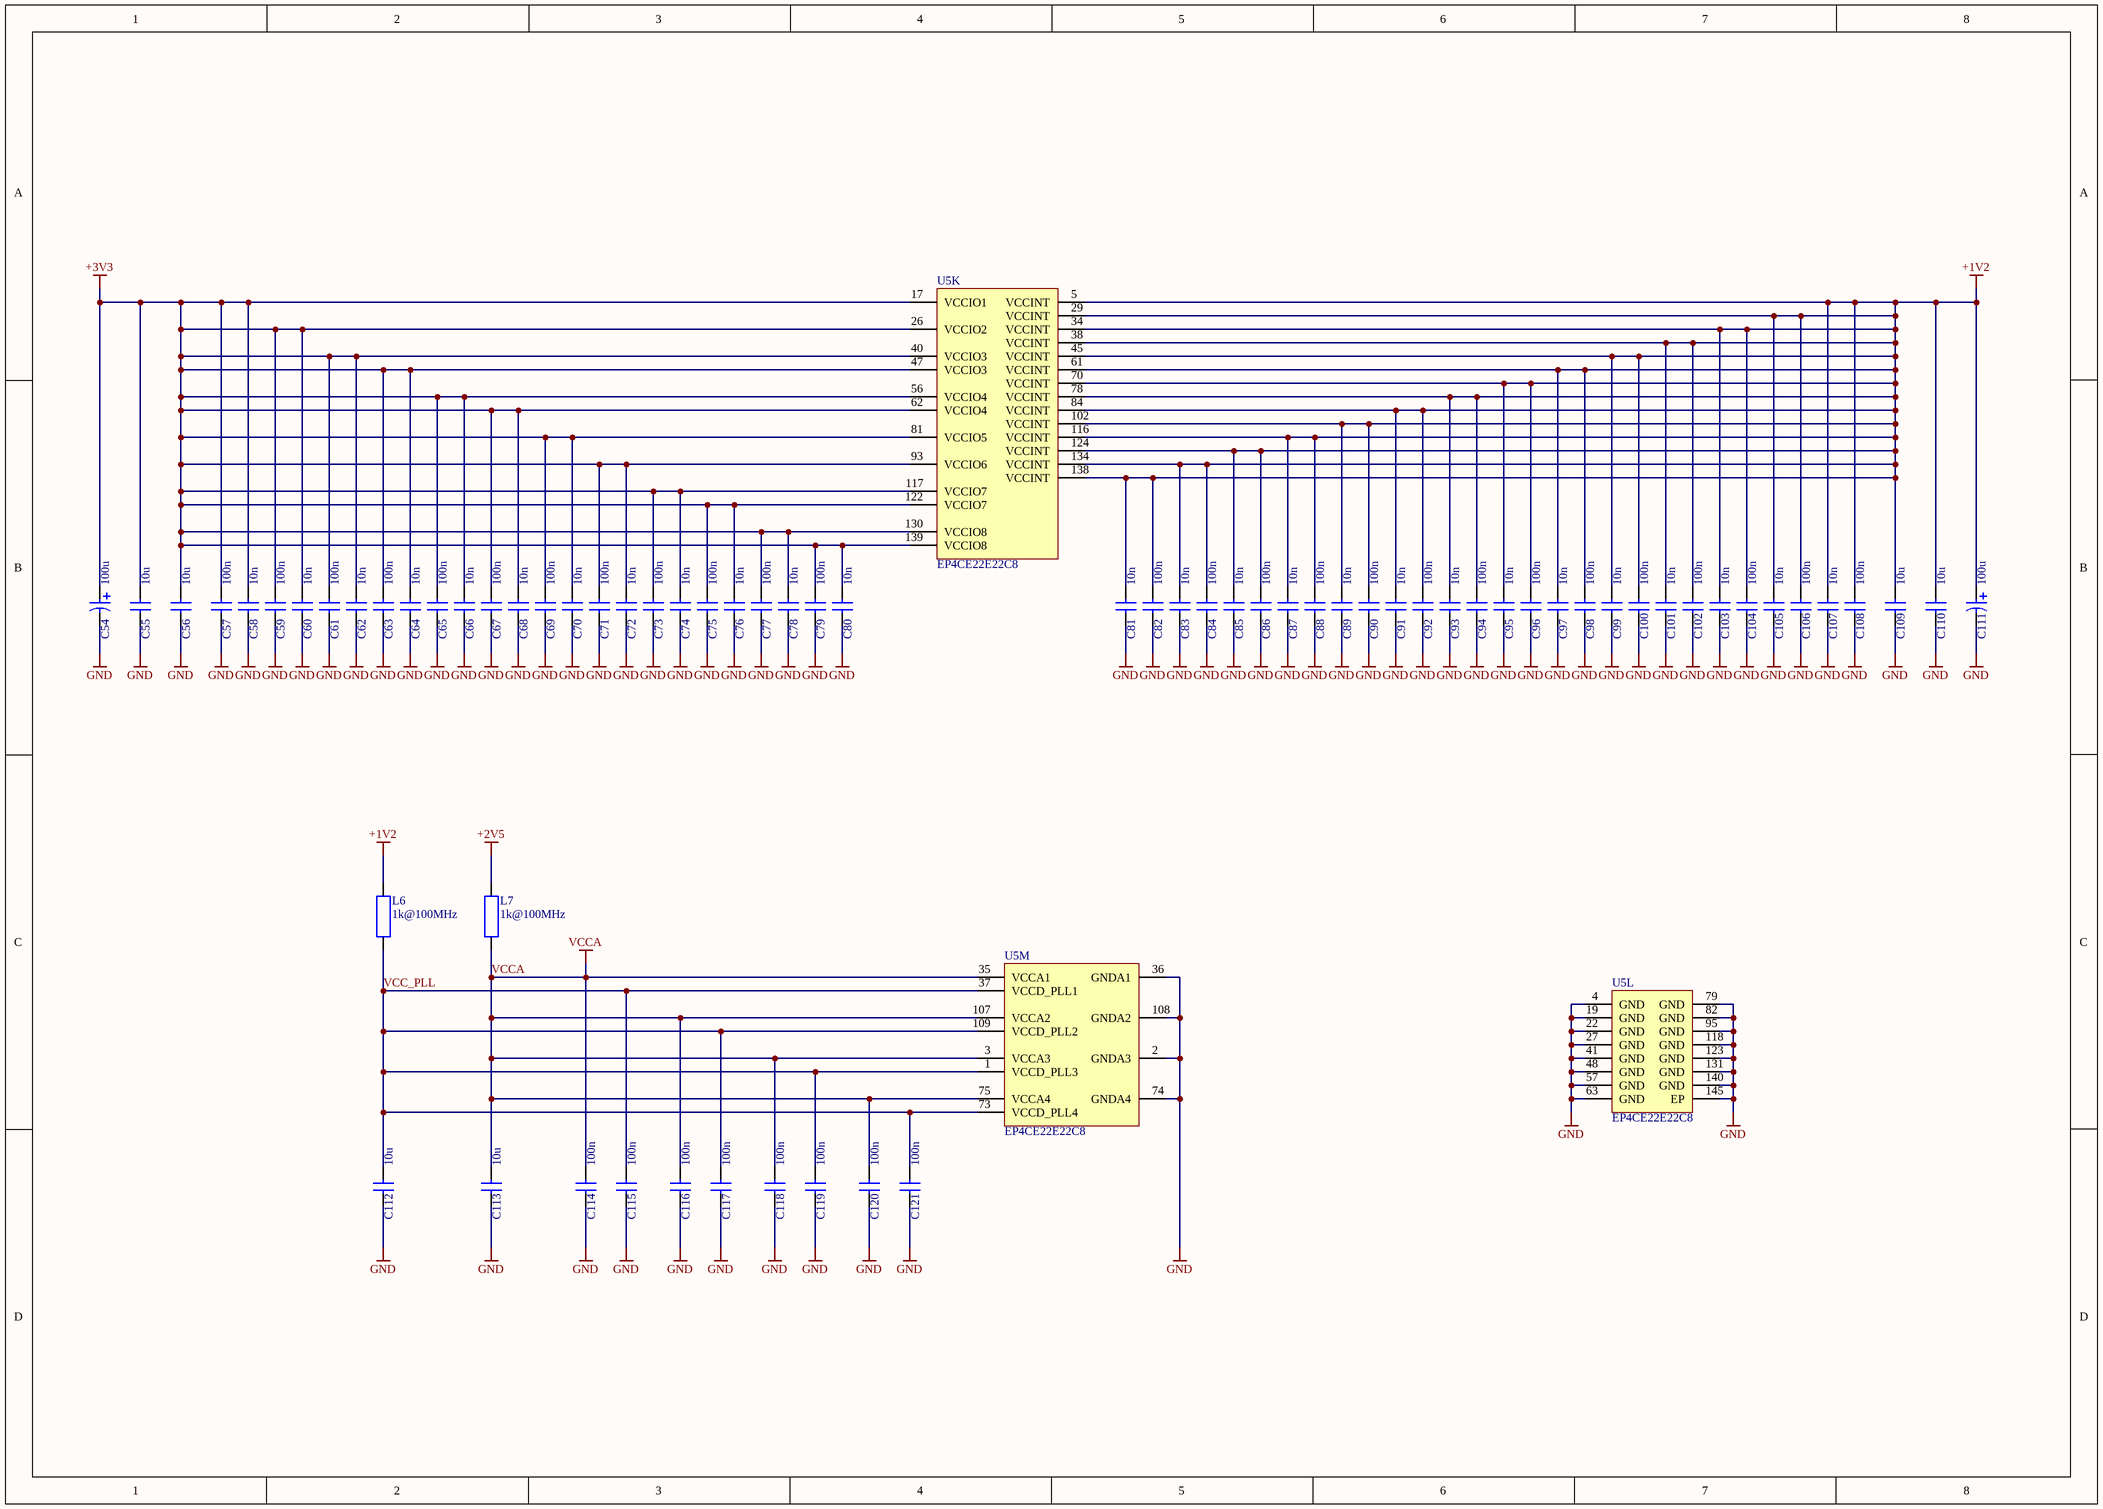
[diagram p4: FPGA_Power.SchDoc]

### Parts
C54  100u  [CAP_Tantalum_D]
C55  10u  [SMD_CAPACITOR_1206]
C56  10u  [SMD_CAPACITOR_1206]
C57  100n  [SMD_CAPACITOR_0402]
C58  10n  [SMD_CAPACITOR_0402]
C59  100n  [SMD_CAPACITOR_0402]
C60  10n  [SMD_CAPACITOR_0402]
C61  100n  [SMD_CAPACITOR_0402]
C62  10n  [SMD_CAPACITOR_0402]
C63  100n  [SMD_CAPACITOR_0402]
C64  10n  [SMD_CAPACITOR_0402]
C65  100n  [SMD_CAPACITOR_0402]
C66  10n  [SMD_CAPACITOR_0402]
C67  100n  [SMD_CAPACITOR_0402]
C68  10n  [SMD_CAPACITOR_0402]
C69  100n  [SMD_CAPACITOR_0402]
C70  10n  [SMD_CAPACITOR_0402]
C71  100n  [SMD_CAPACITOR_0402]
C72  10n  [SMD_CAPACITOR_0402]
C73  100n  [SMD_CAPACITOR_0402]
C74  10n  [SMD_CAPACITOR_0402]
C75  100n  [SMD_CAPACITOR_0402]
C76  10n  [SMD_CAPACITOR_0402]
C77  100n  [SMD_CAPACITOR_0402]
C78  10n  [SMD_CAPACITOR_0402]
C79  100n  [SMD_CAPACITOR_0402]
C80  10n  [SMD_CAPACITOR_0402]
C81  10n  [SMD_CAPACITOR_0402]
C82  100n  [SMD_CAPACITOR_0402]
C83  10n  [SMD_CAPACITOR_0402]
C84  100n  [SMD_CAPACITOR_0402]
C85  10n  [SMD_CAPACITOR_0402]
C86  100n  [SMD_CAPACITOR_0402]
C87  10n  [SMD_CAPACITOR_0402]
C88  100n  [SMD_CAPACITOR_0402]
C89  10n  [SMD_CAPACITOR_0402]
C90  100n  [SMD_CAPACITOR_0402]
C91  10n  [SMD_CAPACITOR_0402]
C92  100n  [SMD_CAPACITOR_0402]
C93  10n  [SMD_CAPACITOR_0402]
C94  100n  [SMD_CAPACITOR_0402]
C95  10n  [SMD_CAPACITOR_0402]
C96  100n  [SMD_CAPACITOR_0402]
C97  10n  [SMD_CAPACITOR_0402]
C98  100n  [SMD_CAPACITOR_0402]
C99  10n  [SMD_CAPACITOR_0402]
C100  100n  [SMD_CAPACITOR_0402]
C101  10n  [SMD_CAPACITOR_0402]
C102  100n  [SMD_CAPACITOR_0402]
C103  10n  [SMD_CAPACITOR_0402]
C104  100n  [SMD_CAPACITOR_0402]
C105  10n  [SMD_CAPACITOR_0402]
C106  100n  [SMD_CAPACITOR_0402]
C107  10n  [SMD_CAPACITOR_0402]
C108  100n  [SMD_CAPACITOR_0402]
C109  10u  [SMD_CAPACITOR_1206]
C110  10u  [SMD_CAPACITOR_1206]
C111  100u  [CAP_Tantalum_D]
C112  10u  [SMD_CAPACITOR_1206]
C113  10u  [SMD_CAPACITOR_1206]
C114  100n  [SMD_CAPACITOR_0402]
C115  100n  [SMD_CAPACITOR_0402]
C116  100n  [SMD_CAPACITOR_0402]
C117  100n  [SMD_CAPACITOR_0402]
C118  100n  [SMD_CAPACITOR_0402]
C119  100n  [SMD_CAPACITOR_0402]
C120  100n  [SMD_CAPACITOR_0402]
C121  100n  [SMD_CAPACITOR_0402]
L6  1k@100MHz  [SMD_RES_0603]
L7  1k@100MHz  [SMD_RES_0603]
U5  EP4CE22E22C8  [EQFP144_N]  (parts K,L,M of 13)

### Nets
+1V2: C81.2 C82.2 C83.2 C84.2 C85.2 C86.2 C87.2 C88.2 C89.2 C90.2 C91.2 C92.2 C93.2 C94.2 C95.2 C96.2 C97.2 C98.2 C99.2 C100.2 C101.2 C102.2 C103.2 C104.2 C105.2 C106.2 C107.2 C108.2 C109.2 C110.2 C111.1 L6.1 U5.5(VCCINT) U5.29(VCCINT) U5.34(VCCINT) U5.38(VCCINT) U5.45(VCCINT) U5.61(VCCINT) U5.70(VCCINT) U5.78(VCCINT) U5.84(VCCINT) U5.102(VCCINT) U5.116(VCCINT) U5.124(VCCINT) U5.134(VCCINT) U5.138(VCCINT)
+2V5: L7.2
+3V3: C54.1 C55.2 C56.2 C57.2 C58.2 C59.2 C60.2 C61.2 C62.2 C63.2 C64.2 C65.2 C66.2 C67.2 C68.2 C69.2 C70.2 C71.2 C72.2 C73.2 C74.2 C75.2 C76.2 C77.2 C78.2 C79.2 C80.2 U5.17(VCCIO1) U5.26(VCCIO2) U5.40(VCCIO3) U5.47(VCCIO3) U5.56(VCCIO4) U5.62(VCCIO4) U5.81(VCCIO5) U5.93(VCCIO6) U5.117(VCCIO7) U5.122(VCCIO7) U5.130(VCCIO8) U5.139(VCCIO8)
GND: C54.2 C55.1 C56.1 C57.1 C58.1 C59.1 C60.1 C61.1 C62.1 C63.1 C64.1 C65.1 C66.1 C67.1 C68.1 C69.1 C70.1 C71.1 C72.1 C73.1 C74.1 C75.1 C76.1 C77.1 C78.1 C79.1 C80.1 C81.1 C82.1 C83.1 C84.1 C85.1 C86.1 C87.1 C88.1 C89.1 C90.1 C91.1 C92.1 C93.1 C94.1 C95.1 C96.1 C97.1 C98.1 C99.1 C100.1 C101.1 C102.1 C103.1 C104.1 C105.1 C106.1 C107.1 C108.1 C109.1 C110.1 C111.2 C112.1 C113.1 C114.1 C115.1 C116.1 C117.1 C118.1 C119.1 C120.1 C121.1 U5.2(GNDA3) U5.4(GND) U5.19(GND) U5.22(GND) U5.27(GND) U5.36(GNDA1) U5.41(GND) U5.48(GND) U5.57(GND) U5.63(GND) U5.74(GNDA4) U5.79(GND) U5.82(GND) U5.95(GND) U5.108(GNDA2) U5.118(GND) U5.123(GND) U5.131(GND) U5.140(GND) U5.145(EP)
VCCA: C113.2 C114.2 C116.2 C118.2 C120.2 L7.1 U5.3(VCCA3) U5.35(VCCA1) U5.75(VCCA4) U5.107(VCCA2)
VCC_PLL: C112.2 C115.2 C117.2 C119.2 C121.2 L6.2 U5.1(VCCD_PLL3) U5.37(VCCD_PLL1) U5.73(VCCD_PLL4) U5.109(VCCD_PLL2)

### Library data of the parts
C54 C111 = Capacitor_pol: pin to pad: 1>+ 2>-
C55-C110 C112-C121 = Capacitor
L6 L7 = EMI_Ferrite_bead
U5 = EP4CE22E22C8: as U5 on sheet FPGA

## Sheet Power.SchDoc
size A4
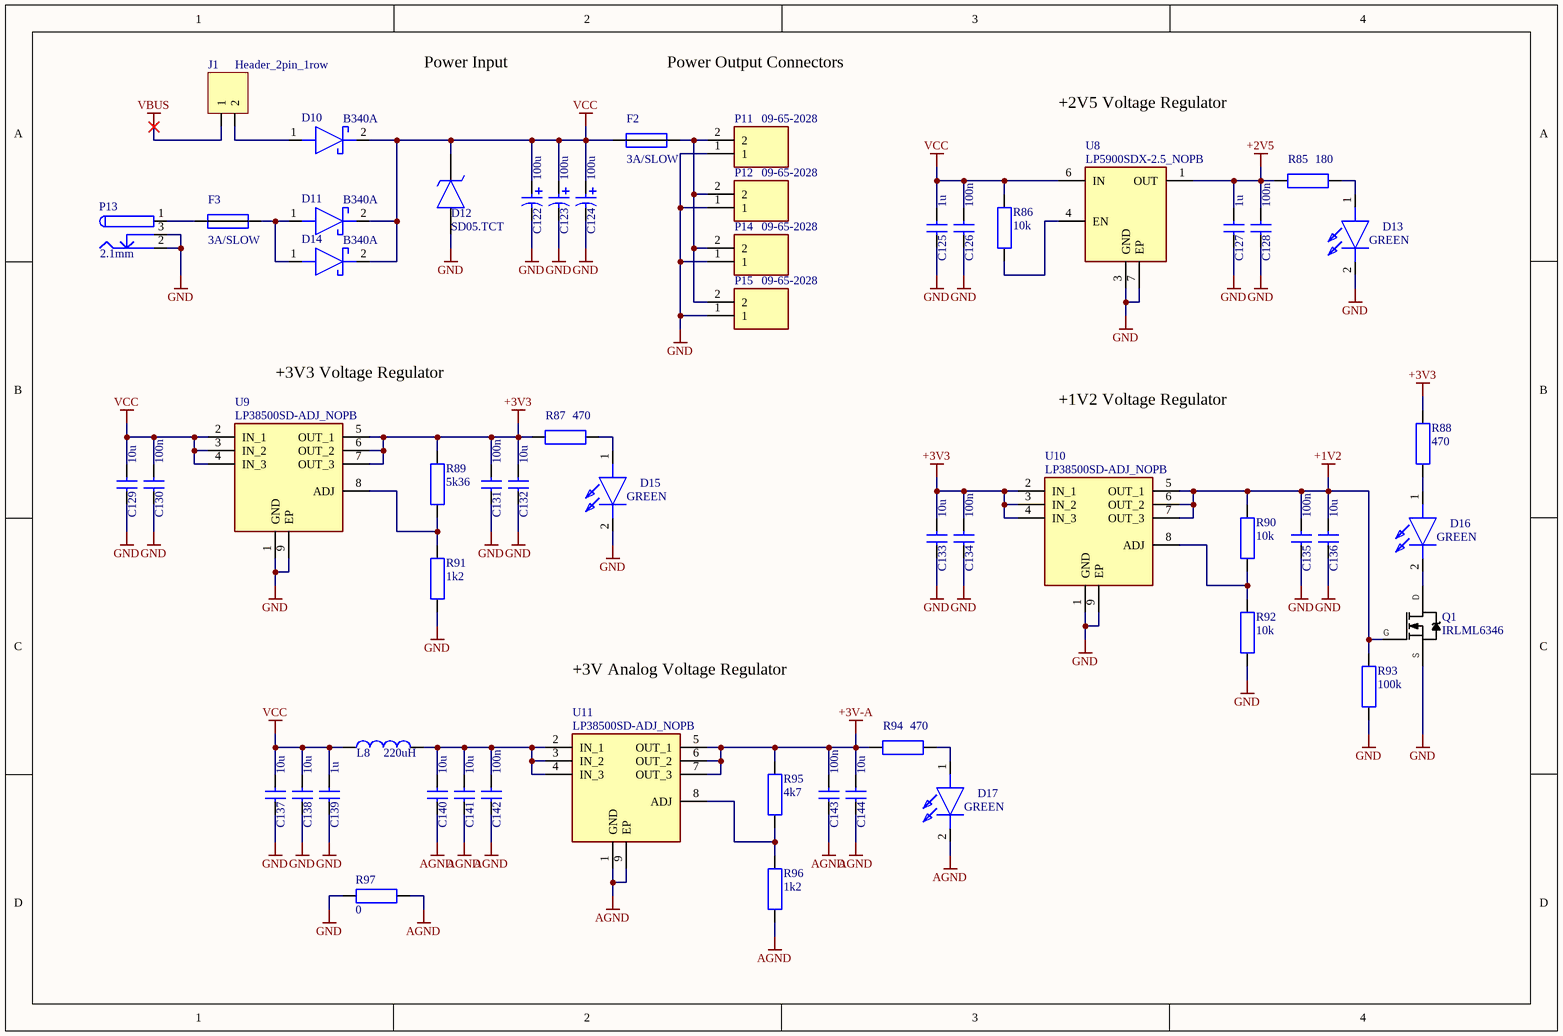
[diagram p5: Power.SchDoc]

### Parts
C122  100u  [CAP_Tantalum_D]
C123  100u  [CAP_Tantalum_D]
C124  100u  [CAP_Tantalum_D]
C125  1u  [SMD_CAPACITOR_0603]
C126  100n  [SMD_CAPACITOR_0603]
C127  1u  [SMD_CAPACITOR_0603]
C128  100n  [SMD_CAPACITOR_0603]
C129  10u  [SMD_CAPACITOR_1206]
C130  100n  [SMD_CAPACITOR_0603]
C131  100n  [SMD_CAPACITOR_0603]
C132  10u  [SMD_CAPACITOR_1206]
C133  10u  [SMD_CAPACITOR_1206]
C134  100n  [SMD_CAPACITOR_0603]
C135  100n  [SMD_CAPACITOR_0603]
C136  10u  [SMD_CAPACITOR_1206]
C137  10u  [SMD_CAPACITOR_1206]
C138  10u  [SMD_CAPACITOR_1206]
C139  1u  [SMD_CAPACITOR_0603]
C140  10u  [SMD_CAPACITOR_1206]
C141  10u  [SMD_CAPACITOR_1206]
C142  100n  [SMD_CAPACITOR_0603]
C143  100n  [SMD_CAPACITOR_0603]
C144  10u  [SMD_CAPACITOR_1206]
D10  B340A  [SMD_DO-214AC]
D11  B340A  [SMD_DO-214AC]
D12  SD05.TCT  [SMD_SOD-323]
D13  GREEN  [SMD_LED_0603]
D14  B340A  [SMD_DO-214AC]
D15  GREEN  [SMD_LED_0603]
D16  GREEN  [SMD_LED_0603]
D17  GREEN  [SMD_LED_0603]
F2  3A/SLOW  [SMD_RESISTOR_1206]
F3  3A/SLOW  [SMD_RESISTOR_1206]
J1  Header_2pin_1row  [61300211121]
L8  220uH  [SMD_INDUCTOR_7.3MM]
P11  09-65-2028  [SHDR2W165P0X396_1X2_716X1062X1425P]
P12  09-65-2028  [SHDR2W165P0X396_1X2_716X1062X1425P]
P13  2.1mm  [THT_POWER_JACK_2.1/2.5]
P14  09-65-2028  [SHDR2W165P0X396_1X2_716X1062X1425P]
P15  09-65-2028  [SHDR2W165P0X396_1X2_716X1062X1425P]
Q1  IRLML6346  [SMD_SOT-23]
R85  180  [SMD_RES_0603]
R86  10k  [SMD_RES_0603]
R87  470  [SMD_RES_0603]
R88  470  [SMD_RES_0603]
R89  5k36  [SMD_RES_0603]
R90  10k  [SMD_RES_0603]
R91  1k2  [SMD_RES_0603]
R92  10k  [SMD_RES_0603]
R93  100k  [SMD_RES_0603]
R94  470  [SMD_RES_0603]
R95  4k7  [SMD_RES_0603]
R96  1k2  [SMD_RES_0603]
R97  0  [SMD_RES_0603]
U8  LP5900SDX-2.5_NOPB  [SON65P220X250X80-7N]
U9  LP38500SD-ADJ_NOPB  [SON50P300X250X80-9N]
U10  LP38500SD-ADJ_NOPB  [SON50P300X250X80-9N]
U11  LP38500SD-ADJ_NOPB  [SON50P300X250X80-9N]

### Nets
+1V2: C135.2 C136.2 Q1.G R90.2 R93.2 U10.5(OUT_1) U10.6(OUT_2) U10.7(OUT_3)
+2V5: C127.2 C128.2 R85.2 U8.1(OUT)
+3V3: C131.2 C132.2 C133.2 C134.2 R87.2 R88.2 R89.2 U9.5(OUT_1) U9.6(OUT_2) U9.7(OUT_3) U10.2(IN_1) U10.3(IN_2) U10.4(IN_3)
+3V-A: C143.2 C144.2 R94.2 R95.2 U11.5(OUT_1) U11.6(OUT_2) U11.7(OUT_3)
AGND: C140.1 C141.1 C142.1 C143.1 C144.1 D17.2(K) R96.1 R97.1 U11.1(GND) U11.9(EP)
GND: C122.2 C123.2 C124.2 C125.1 C126.1 C127.1 C128.1 C129.1 C130.1 C131.1 C132.1 C133.1 C134.1 C135.1 C136.1 C137.1 C138.1 C139.1 D12.1(A) D13.2(K) D15.2(K) P11.1 P12.1 P13.2 P13.3 P14.1 P15.1 Q1.S R91.1 R92.1 R93.1 R97.2 U8.3(GND) U8.7(EP) U9.1(GND) U9.9(EP) U10.1(GND) U10.9(EP)
VBUS: J1.1
VCC: C122.1 C123.1 C124.1 C125.2 C126.2 C129.2 C130.2 C137.2 C138.2 C139.2 D10.2(K) D11.2(K) D12.2(K) D14.2(K) F2.1 L8.1 R86.2 U8.6(IN) U9.2(IN_1) U9.3(IN_2) U9.4(IN_3)
NetC140_2: C140.2 C141.2 C142.2 L8.2 U11.2(IN_1) U11.3(IN_2) U11.4(IN_3)
NetD10_1: D10.1(A) J1.2
NetD11_1: D11.1(A) D14.1(A) F3.2
NetD13_1: D13.1(A) R85.1
NetD15_1: D15.1(A) R87.1
NetD16_1: D16.1(A) R88.1
NetD16_2: D16.2(K) Q1.D
NetD17_1: D17.1(A) R94.1
NetF2_2: F2.2 P11.2 P12.2 P14.2 P15.2
NetF3_1: F3.1 P13.1
NetR86_1: R86.1 U8.4(EN)
NetR89_1: R89.1 R91.2 U9.8(ADJ)
NetR90_1: R90.1 R92.2 U10.8(ADJ)
NetR95_1: R95.1 R96.2 U11.8(ADJ)

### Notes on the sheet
- Power Input
- Power Output Connectors
- +2V5 Voltage Regulator
- +3V3 Voltage Regulator
- +1V2 Voltage Regulator
- +3V Analog Voltage Regulator

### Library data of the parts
C122-C124 = Capacitor_pol: pin to pad: 1>+ 2>-
C125-C144 = Capacitor
D10 D11 D14 = Schottky_Diode
D12 = TVS_Diode_unidirect
D13 D15-D17 = LED
F2 F3 = Fuse
J1 = Header_2pin_1row: Manufacturer: Wurth Electronics
L8 = Inductor
P11 P12 P14 P15 = 09-65-2028: Connector; Manufacturer_Name: Molex; Allied_Number: 70374002
P13 = Power_JACK_2.1/2.5: Low Voltage Power Supply Connector
Q1 = Transistor_N-Mosfet: pin to pad: D>3 G>1 S>2
R85-R97 = Resistor
U8 = LP5900SDX-2.5_NOPB: LDO
U9-U11 = LP38500SD-ADJ_NOPB: LDO

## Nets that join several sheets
+1V2: FPGA_Power (46 pins), Power (8 pins)
+2V5: FPGA (P5.4 R38.2 R39.2), FPGA_Power (L7.2), Power (C127.2 C128.2 R85.2 U8.1)
+3V3: ADC (C3.1 C5.1 C7.1 U1.21), FPGA (32 pins), FPGA_Power (39 pins), Power (13 pins)
+3V-A: ADC (L1.2 L2.2 R3.2), Power (7 pins)
AGND: Main (P10.2 P10.3 P10.4 P10.5), ADC (22 pins), Power (10 pins)
GND: ADC (5 pins), Communication (40 pins), FPGA (50 pins), FPGA_Power (88 pins), Power (38 pins)
VBUS: Communication (6 pins), Power (J1.1)
VCCA: FPGA (R28.2 R29.2 R30.2), FPGA_Power (10 pins)
/RESET: Communication (C32.2 R15.1 U3.34), FPGA (U5.7)
NetC16_2: Main (P10.1), ADC (C16.2 R6.1 R9.2)
NetC41_2: Communication (C41.2 R25.1 R26.2), FPGA (U5.23)
NetR41_2: Communication (U3.33), FPGA (R41.2)
NetR42_2: Communication (U3.32), FPGA (R42.2)
NetR43_2: Communication (U3.31), FPGA (R43.2)
NetR44_2: Communication (U3.30), FPGA (R44.2)
NetR45_2: Communication (U3.29), FPGA (R45.2)
NetR51_2: Communication (U3.28), FPGA (R51.2)
NetR54_2: Communication (U3.27), FPGA (R54.2)
NetR55_2: Communication (U3.26), FPGA (R55.2)
NetR56_2: Communication (U3.25), FPGA (R56.2)
NetR61_2: Communication (U3.21), FPGA (R61.2)
NetR66_2: Communication (U3.20), FPGA (R66.2)
NetR67_2: Communication (U3.19), FPGA (R67.2)
NetR68_2: Communication (U3.18), FPGA (R68.2)
NetR71_2: Communication (U3.17), FPGA (R71.2)
NetR75_2: Communication (U3.16), FPGA (R75.2)
NetR78_2: Communication (U3.15), FPGA (R78.2)
NetR79_2: Communication (U3.14), FPGA (R79.2)
NetR80_2: Communication (U3.13), FPGA (R80.2)
NetU1_9: ADC (U1.9), FPGA (U5.30)
NetU1_10: ADC (U1.10), FPGA (U5.58)
NetU1_11: ADC (U1.11), FPGA (U5.51)
NetU1_16: ADC (U1.16), FPGA (U5.50)
NetU1_17: ADC (U1.17), FPGA (U5.49)
NetU1_18: ADC (U1.18), FPGA (U5.46)
NetU1_19: ADC (U1.19), FPGA (U5.44)
NetU1_22: ADC (U1.22), FPGA (U5.43)
NetU1_23: ADC (U1.23), FPGA (U5.42)
NetU1_24: ADC (U1.24), FPGA (U5.39)
NetU1_25: ADC (U1.25), FPGA (U5.33)
NetU1_26: ADC (U1.26), FPGA (U5.32)
NetU1_27: ADC (U1.27), FPGA (U5.31)
NetU1_28: ADC (U1.28), FPGA (U5.28)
